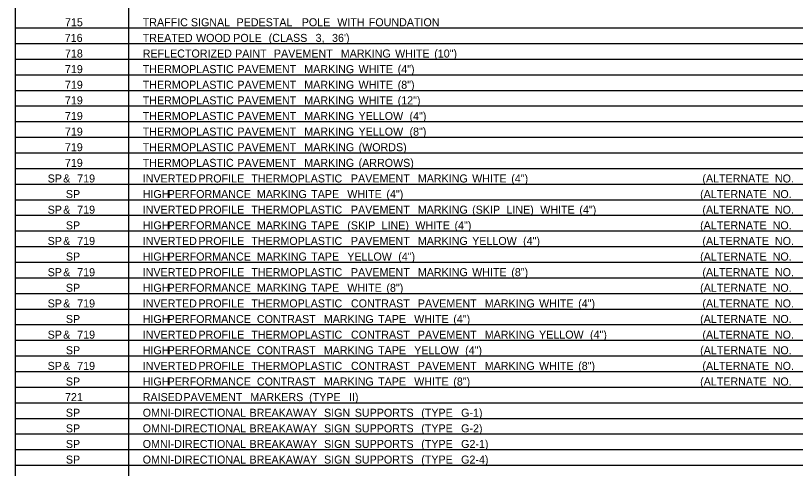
# Model space of a CAD drawing. Extents: x 1226603 to 1228117, y 151305 to 152343.
# Drawn here: x 1227295.3 to 1227709.6, y 151561 to 151801.3 of the extents above; entities that cross this region are included whole.
import ezdxf

# ---------------------------------------------------------------- set-up
doc = ezdxf.new("R2010")
doc.units = 0
doc.layers.add('R_Dimension', color=7, linetype='Continuous')

msp = doc.modelspace()

# ---------------------------------------------------------------- linework, layer by layer
at = {"layer": 'R_Dimension'}
for p, q in [((1227295.33, 151330.69), (1227295.33, 152231.95)), ((1227355.42, 151330.69), (1227355.42, 152231.95)), ((1227295.33, 151794.79), (1227925.18, 151794.79)), ((1227295.33, 151786.5), (1227925.18, 151786.5)), ((1227295.33, 151778.21), (1227925.18, 151778.21)), ((1227295.33, 151769.93), (1227925.18, 151769.93)), ((1227295.33, 151761.64), (1227925.18, 151761.64)), ((1227295.33, 151753.35), (1227925.18, 151753.35)), ((1227295.33, 151745.06), (1227925.18, 151745.06)), ((1227295.33, 151736.78), (1227925.18, 151736.78)), ((1227295.33, 151728.49), (1227925.18, 151728.49)), ((1227295.33, 151720.2), (1227925.18, 151720.2)), ((1227295.33, 151711.91), (1227925.18, 151711.91)), ((1227295.33, 151703.63), (1227925.18, 151703.63)), ((1227295.33, 151695.34), (1227925.18, 151695.34)), ((1227295.33, 151687.05), (1227925.18, 151687.05)), ((1227295.33, 151678.76), (1227925.18, 151678.76)), ((1227295.33, 151670.48), (1227925.18, 151670.48)), ((1227295.33, 151662.19), (1227925.18, 151662.19)), ((1227295.33, 151653.9), (1227925.18, 151653.9)), ((1227295.33, 151645.61), (1227925.18, 151645.61)), ((1227295.33, 151637.33), (1227925.18, 151637.33)), ((1227295.33, 151629.04), (1227925.18, 151629.04)), ((1227295.33, 151620.75), (1227925.18, 151620.75)), ((1227295.33, 151612.46), (1227925.18, 151612.46)), ((1227295.33, 151604.18), (1227925.18, 151604.18)), ((1227295.33, 151595.89), (1227925.18, 151595.89)), ((1227295.33, 151587.6), (1227925.18, 151587.6)), ((1227295.33, 151579.31), (1227925.18, 151579.31)), ((1227295.33, 151571.03), (1227925.18, 151571.03)), ((1227295.33, 151562.74), (1227925.18, 151562.74))]:
    msp.add_line(p, q, dxfattribs=at)

# ---------------------------------------------------------------- texts
for s, p in [('715', (1227321.56, 151795.64)), ('TRAFFIC', (1227362.87, 151795.64)), (' SIGNAL', (1227386.87, 151795.64)), (' PEDESTAL', (1227411.13, 151795.64)), (' POLE', (1227445.77, 151795.64)), (' WITH', (1227464.61, 151795.64)), (' FOUNDATION', (1227481.37, 151795.64)), ('716', (1227321.44, 151787.35)), ('TREATED', (1227362.87, 151787.35)), (' WOOD', (1227389.61, 151787.35)), (' POLE', (1227409.36, 151787.35)), (' (CLASS', (1227428.2, 151787.35)), (' 3,', (1227453.13, 151787.35)), (" 36')", (1227461.86, 151787.35)), ('718', (1227321.56, 151779.06)), ('REFLECTORIZED', (1227362.87, 151779.06)), (' PAINT', (1227410.36, 151779.06)), (' PAVEMENT', (1227430.98, 151779.06)), (' MARKING', (1227466.51, 151779.06)), (' WHITE', (1227495.36, 151779.06)), (' (10")', (1227516.14, 151779.06)), ('719', (1227321.54, 151770.78)), ('THERMOPLASTIC', (1227362.87, 151770.78)), (' PAVEMENT', (1227411.57, 151770.78)), (' MARKING', (1227447.11, 151770.78)), (' WHITE', (1227475.95, 151770.78)), (' (4")', (1227496.73, 151770.78)), ('719', (1227321.54, 151762.49)), ('THERMOPLASTIC', (1227362.87, 151762.49)), (' PAVEMENT', (1227411.57, 151762.49)), (' MARKING', (1227447.11, 151762.49)), (' WHITE', (1227475.95, 151762.49)), (' (8")', (1227496.73, 151762.49)), ('719', (1227321.54, 151754.2)), ('THERMOPLASTIC', (1227362.87, 151754.2)), (' PAVEMENT', (1227411.57, 151754.2)), (' MARKING', (1227447.11, 151754.2)), (' WHITE', (1227475.95, 151754.2)), (' (12")', (1227496.73, 151754.2)), ('719', (1227321.54, 151745.91)), ('THERMOPLASTIC', (1227362.87, 151745.91)), (' PAVEMENT', (1227411.57, 151745.91)), (' MARKING', (1227447.11, 151745.91)), (' YELLOW', (1227475.95, 151745.91)), (' (4")', (1227503.02, 151745.91)), ('719', (1227321.54, 151737.63)), ('THERMOPLASTIC', (1227362.87, 151737.63)), (' PAVEMENT', (1227411.57, 151737.63)), (' MARKING', (1227447.11, 151737.63)), (' YELLOW', (1227475.95, 151737.63)), (' (8")', (1227503.02, 151737.63)), ('719', (1227321.54, 151729.34)), ('THERMOPLASTIC', (1227362.87, 151729.34)), (' PAVEMENT', (1227411.57, 151729.34)), (' MARKING', (1227447.11, 151729.34)), (' (WORDS)', (1227475.95, 151729.34)), ('719', (1227321.54, 151721.05)), ('THERMOPLASTIC', (1227362.87, 151721.05)), (' PAVEMENT', (1227411.57, 151721.05)), (' MARKING', (1227447.11, 151721.05)), (' (ARROWS)', (1227475.95, 151721.05)), ('SP', (1227312.36, 151712.76)), (' &', (1227319.02, 151712.76)), (' 719', (1227326.48, 151712.76)), ('INVERTED', (1227362.87, 151712.76)), (' PROFILE', (1227390.88, 151712.76)), (' THERMOPLASTIC', (1227418.96, 151712.76)), (' PAVEMENT', (1227471.9, 151712.76)), (' MARKING', (1227507.44, 151712.76)), (' WHITE', (1227536.29, 151712.76)), (' (4")', (1227557.07, 151712.76)), ('(ALTERNATE', (1227660.19, 151712.76)), (' NO.', (1227697.13, 151712.76)), ('SP', (1227322.04, 151704.48)), ('HIGH', (1227362.87, 151704.48)), (' PERFORMANCE', (1227374.52, 151704.48)), (' MARKING', (1227421.94, 151704.48)), (' TAPE', (1227450.79, 151704.48)), (' WHITE', (1227469.96, 151704.48)), (' (4")', (1227490.74, 151704.48)), ('(ALTERNATE', (1227658.98, 151704.48)), (' NO.', (1227695.93, 151704.48)), ('SP', (1227312.36, 151696.19)), (' &', (1227319.02, 151696.19)), (' 719', (1227326.48, 151696.19)), ('INVERTED', (1227362.87, 151696.19)), (' PROFILE', (1227390.88, 151696.19)), (' THERMOPLASTIC', (1227418.96, 151696.19)), (' PAVEMENT', (1227471.9, 151696.19)), (' MARKING', (1227507.44, 151696.19)), (' (SKIP', (1227536.29, 151696.19)), (' LINE)', (1227554.49, 151696.19)), (' WHITE', (1227572.46, 151696.19)), (' (4")', (1227593.25, 151696.19)), ('(ALTERNATE', (1227660.19, 151696.19)), (' NO.', (1227697.13, 151696.19)), ('SP', (1227322.04, 151687.9)), ('HIGH', (1227362.87, 151687.9)), (' PERFORMANCE', (1227374.52, 151687.9)), (' MARKING', (1227421.94, 151687.9)), (' TAPE', (1227450.79, 151687.9)), (' (SKIP', (1227469.96, 151687.9)), (' LINE)', (1227488.17, 151687.9)), (' WHITE', (1227506.14, 151687.9)), (' (4")', (1227526.92, 151687.9)), ('(ALTERNATE', (1227658.98, 151687.9)), (' NO.', (1227695.93, 151687.9)), ('SP', (1227312.36, 151679.61)), (' &', (1227319.02, 151679.61)), (' 719', (1227326.48, 151679.61)), ('INVERTED', (1227362.87, 151679.61)), (' PROFILE', (1227390.88, 151679.61)), (' THERMOPLASTIC', (1227418.96, 151679.61)), (' PAVEMENT', (1227471.9, 151679.61)), (' MARKING', (1227507.44, 151679.61)), (' YELLOW', (1227536.29, 151679.61)), (' (4")', (1227563.36, 151679.61)), ('(ALTERNATE', (1227660.19, 151679.61)), (' NO.', (1227697.13, 151679.61)), ('SP', (1227322.04, 151671.33)), ('HIGH', (1227362.87, 151671.33)), (' PERFORMANCE', (1227374.52, 151671.33)), (' MARKING', (1227421.94, 151671.33)), (' TAPE', (1227450.79, 151671.33)), (' YELLOW', (1227469.96, 151671.33)), (' (4")', (1227497.03, 151671.33)), ('(ALTERNATE', (1227658.98, 151671.33)), (' NO.', (1227695.93, 151671.33)), ('SP', (1227312.36, 151663.04)), (' &', (1227319.02, 151663.04)), (' 719', (1227326.48, 151663.04)), ('INVERTED', (1227362.87, 151663.04)), (' PROFILE', (1227390.88, 151663.04)), (' THERMOPLASTIC', (1227418.96, 151663.04)), (' PAVEMENT', (1227471.9, 151663.04)), (' MARKING', (1227507.44, 151663.04)), (' WHITE', (1227536.29, 151663.04)), (' (8")', (1227557.07, 151663.04)), ('(ALTERNATE', (1227660.19, 151663.04)), (' NO.', (1227697.13, 151663.04)), ('SP', (1227322.04, 151654.75)), ('HIGH', (1227362.87, 151654.75)), (' PERFORMANCE', (1227374.52, 151654.75)), (' MARKING', (1227421.94, 151654.75)), (' TAPE', (1227450.79, 151654.75)), (' WHITE', (1227469.96, 151654.75)), (' (8")', (1227490.74, 151654.75)), ('(ALTERNATE', (1227658.98, 151654.75)), (' NO.', (1227695.93, 151654.75)), ('SP', (1227312.36, 151646.46)), (' &', (1227319.02, 151646.46)), (' 719', (1227326.48, 151646.46)), ('INVERTED', (1227362.87, 151646.46)), (' PROFILE', (1227390.88, 151646.46)), (' THERMOPLASTIC', (1227418.96, 151646.46)), (' CONTRAST', (1227471.9, 151646.46)), (' PAVEMENT', (1227507.44, 151646.46)), (' MARKING', (1227542.98, 151646.46)), (' WHITE', (1227571.83, 151646.46)), (' (4")', (1227592.61, 151646.46)), ('(ALTERNATE', (1227660.19, 151646.46)), (' NO.', (1227697.13, 151646.46)), ('SP', (1227322.04, 151638.18)), ('HIGH', (1227362.87, 151638.18)), (' PERFORMANCE', (1227374.52, 151638.18)), (' CONTRAST', (1227421.94, 151638.18)), (' MARKING', (1227457.48, 151638.18)), (' TAPE', (1227486.33, 151638.18)), (' WHITE', (1227505.5, 151638.18)), (' (4")', (1227526.28, 151638.18)), ('(ALTERNATE', (1227658.98, 151638.18)), (' NO.', (1227695.93, 151638.18)), ('SP', (1227312.36, 151629.89)), (' &', (1227319.02, 151629.89)), (' 719', (1227326.48, 151629.89)), ('INVERTED', (1227362.87, 151629.89)), (' PROFILE', (1227390.88, 151629.89)), (' THERMOPLASTIC', (1227418.96, 151629.89)), (' CONTRAST', (1227471.9, 151629.89)), (' PAVEMENT', (1227507.44, 151629.89)), (' MARKING', (1227542.98, 151629.89)), (' YELLOW', (1227571.83, 151629.89)), (' (4")', (1227598.9, 151629.89)), ('(ALTERNATE', (1227660.19, 151629.89)), (' NO.', (1227697.13, 151629.89)), ('SP', (1227322.04, 151621.6)), ('HIGH', (1227362.87, 151621.6)), (' PERFORMANCE', (1227374.52, 151621.6)), (' CONTRAST', (1227421.94, 151621.6)), (' MARKING', (1227457.48, 151621.6)), (' TAPE', (1227486.33, 151621.6)), (' YELLOW', (1227505.5, 151621.6)), (' (4")', (1227532.57, 151621.6)), ('(ALTERNATE', (1227658.98, 151621.6)), (' NO.', (1227695.93, 151621.6)), ('SP', (1227312.36, 151613.31)), (' &', (1227319.02, 151613.31)), (' 719', (1227326.48, 151613.31)), ('INVERTED', (1227362.87, 151613.31)), (' PROFILE', (1227390.88, 151613.31)), (' THERMOPLASTIC', (1227418.96, 151613.31)), (' CONTRAST', (1227471.9, 151613.31)), (' PAVEMENT', (1227507.44, 151613.31)), (' MARKING', (1227542.98, 151613.31)), (' WHITE', (1227571.83, 151613.31)), (' (8")', (1227592.61, 151613.31)), ('(ALTERNATE', (1227660.19, 151613.31)), (' NO.', (1227697.13, 151613.31)), ('SP', (1227322.04, 151605.03)), ('HIGH', (1227362.87, 151605.03)), (' PERFORMANCE', (1227374.52, 151605.03)), (' CONTRAST', (1227421.94, 151605.03)), (' MARKING', (1227457.48, 151605.03)), (' TAPE', (1227486.33, 151605.03)), (' WHITE', (1227505.5, 151605.03)), (' (8")', (1227526.28, 151605.03)), ('(ALTERNATE', (1227658.98, 151605.03)), (' NO.', (1227695.93, 151605.03)), ('721', (1227321.56, 151596.74)), ('RAISED', (1227362.87, 151596.74)), (' PAVEMENT', (1227382.92, 151596.74)), (' MARKERS', (1227418.46, 151596.74)), (' (TYPE', (1227449.68, 151596.74)), (' II)', (1227470.87, 151596.74)), ('SP', (1227322.04, 151588.45)), ('OMNI-DIRECTIONAL', (1227362.87, 151588.45)), (' BREAKAWAY', (1227418.02, 151588.45)), (' SIGN', (1227457.61, 151588.45)), (' SUPPORTS', (1227473.94, 151588.45)), (' (TYPE', (1227509.25, 151588.45)), (' G-1)', (1227530.43, 151588.45)), ('SP', (1227322.04, 151580.16)), ('OMNI-DIRECTIONAL', (1227362.87, 151580.16)), (' BREAKAWAY', (1227418.02, 151580.16)), (' SIGN', (1227457.61, 151580.16)), (' SUPPORTS', (1227473.94, 151580.16)), (' (TYPE', (1227509.25, 151580.16)), (' G-2)', (1227530.43, 151580.16)), ('SP', (1227322.04, 151571.88)), ('OMNI-DIRECTIONAL', (1227362.87, 151571.88)), (' BREAKAWAY', (1227418.02, 151571.88)), (' SIGN', (1227457.61, 151571.88)), (' SUPPORTS', (1227473.94, 151571.88)), (' (TYPE', (1227509.25, 151571.88)), (' G2-1)', (1227530.43, 151571.88)), ('SP', (1227322.04, 151563.59)), ('OMNI-DIRECTIONAL', (1227362.87, 151563.59)), (' BREAKAWAY', (1227418.02, 151563.59)), (' SIGN', (1227457.61, 151563.59)), (' SUPPORTS', (1227473.94, 151563.59)), (' (TYPE', (1227509.25, 151563.59)), (' G2-4)', (1227530.43, 151563.59))]:
    msp.add_text(s, height=4.25, dxfattribs=at).set_placement(p)

doc.saveas('drawing.dxf')
